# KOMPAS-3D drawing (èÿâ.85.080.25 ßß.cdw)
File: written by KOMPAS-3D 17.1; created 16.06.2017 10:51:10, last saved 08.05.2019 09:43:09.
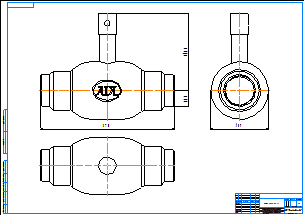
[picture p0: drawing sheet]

Sheet 1: A1, landscape

Title block, sheet 1: name: КШГ.85.080.25 сс; material: Внимание! Данный продукт является объектом авторского права ООО «Торговый Дом АДЛ». / Запрещается изменение, копирование, распространение / (в том числе путем копирования на другие сайты и ресурсы в Интернете) / или любое иное использование информации и объектов без предварительного / согласия правообладателя (ООО «Торговый Дом АДЛ»).; scale: 1:1; sheets: 1; organisation: ООО "Торговый дом АДЛ"; sheet format: A1; stored path: C:\Users\tra\Desktop\2д чертежи\Шаровые краны БИВАЛ\КШ_Бивал_серия_82_85\KOMPAS 2D\КШГ.85.080.25 сс.cdw

Views: Спереди 1, Проекционный вид 2, Проекционный вид 3
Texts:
  Klimkovich
  ADL
Dimensions and other numbers on the sheet: 370; 214,6; 44,5; 159; 1:1; 1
